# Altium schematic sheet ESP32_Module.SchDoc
size 431 x 279 mm; Organization: ORGANIZATION; Address1: ADDRESS 1; Address2: ADDRESS 2; Address3: ADDRESS 3; Address4: ADDRESS 4; Revision: -; SheetNumber: 4; SheetTotal: 4; ENG_APP_DATE: --/--/--; DSN_APP_DATE: --/--/--; CHK_APP_DATE: --/--/--
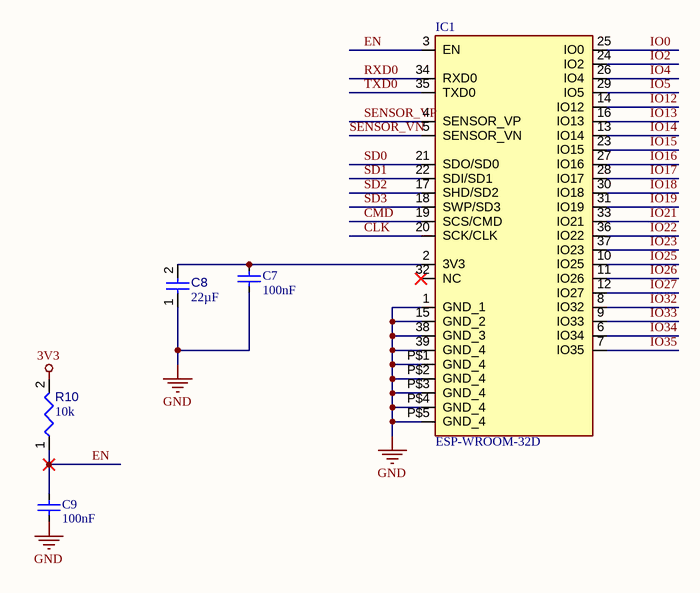
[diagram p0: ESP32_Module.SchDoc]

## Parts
C7  value 100nF  [0603C_L]  (hidden comment: Cap100nF_50V_0603)
C8  value 22µF  [CAPC0805(2012)145_L]  (hidden comment: Capacitor 22µF +/-40% 16V 0805)
C9  value 100nF  [0603C_L]  (hidden comment: Cap100nF_50V_0603)
IC1  ESP-WROOM-32D  [ESPWROOM32D]
R10  value 10k  [RESC0402(1005)_L]  (hidden comment: Resistor 10K  +/-1 % 0402 63 mW)

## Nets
3V3: R10.2
GND: C7.1 C8.1 C9.1 IC1.1(GND_1) IC1.15(GND_2) IC1.38(GND_3) IC1.39(GND_4) IC1.P$1(GND_4) IC1.P$2(GND_4) IC1.P$3(GND_4) IC1.P$4(GND_4) IC1.P$5(GND_4)
CLK: IC1.20(SCK/CLK)
CMD: IC1.19(SCS/CMD)
EN: C9.2 IC1.3(EN) R10.1
IO0: IC1.25(IO0)
IO2: IC1.24(IO2)
IO4: IC1.26(IO4)
IO5: IC1.29(IO5)
IO12: IC1.14(IO12)
IO13: IC1.16(IO13)
IO14: IC1.13(IO14)
IO15: IC1.23(IO15)
IO16: IC1.27(IO16)
IO17: IC1.28(IO17)
IO18: IC1.30(IO18)
IO19: IC1.31(IO19)
IO21: IC1.33(IO21)
IO22: IC1.36(IO22)
IO23: IC1.37(IO23)
IO25: IC1.10(IO25)
IO26: IC1.11(IO26)
IO27: IC1.12(IO27)
IO32: IC1.8(IO32)
IO33: IC1.9(IO33)
IO34: IC1.6(IO34)
IO35: IC1.7(IO35)
RXD0: IC1.34(RXD0)
SD0: IC1.21(SDO/SD0)
SD1: IC1.22(SDI/SD1)
SD2: IC1.17(SHD/SD2)
SD3: IC1.18(SWP/SD3)
SENSOR_VN: IC1.5(SENSOR_VN)
SENSOR_VP: IC1.4(SENSOR_VP)
TXD0: IC1.35(TXD0)
NetC7_2: C7.2 C8.2 IC1.2(3V3)

Not connected (* = marked no-connect by the designer): IC1 32(NC)*

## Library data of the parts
C7 C9 = CMP-001-00084-1: Ceramic Capacitor, Multilayer, Ceramic, 50V, 80% +Tol, 20% -Tol, Y5V, -82/+22% TC, 0.1uF, Surface Mount, 0603; Manufacturer: Yageo; Manufacturer Part Number: CC0603ZRY5V9BB104; Multilayer: Yes
C8 = CMP-001-00081-4: Chip Capacitor, 22µF +/-40%, 16V, 0805, Thickness 1.45 mm; Tolerance: 5%
IC1 = ESP-WROOM-32D: WiFi / 802.11 Modules; MF: Espressif Systems
R10 = CMP-009-00149-3: Chip Resistor, 10 kOhms, +/-1 %, 63 mW, -55 to 125 degC, 0402; Power: 63mW; Tolerance: 1%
